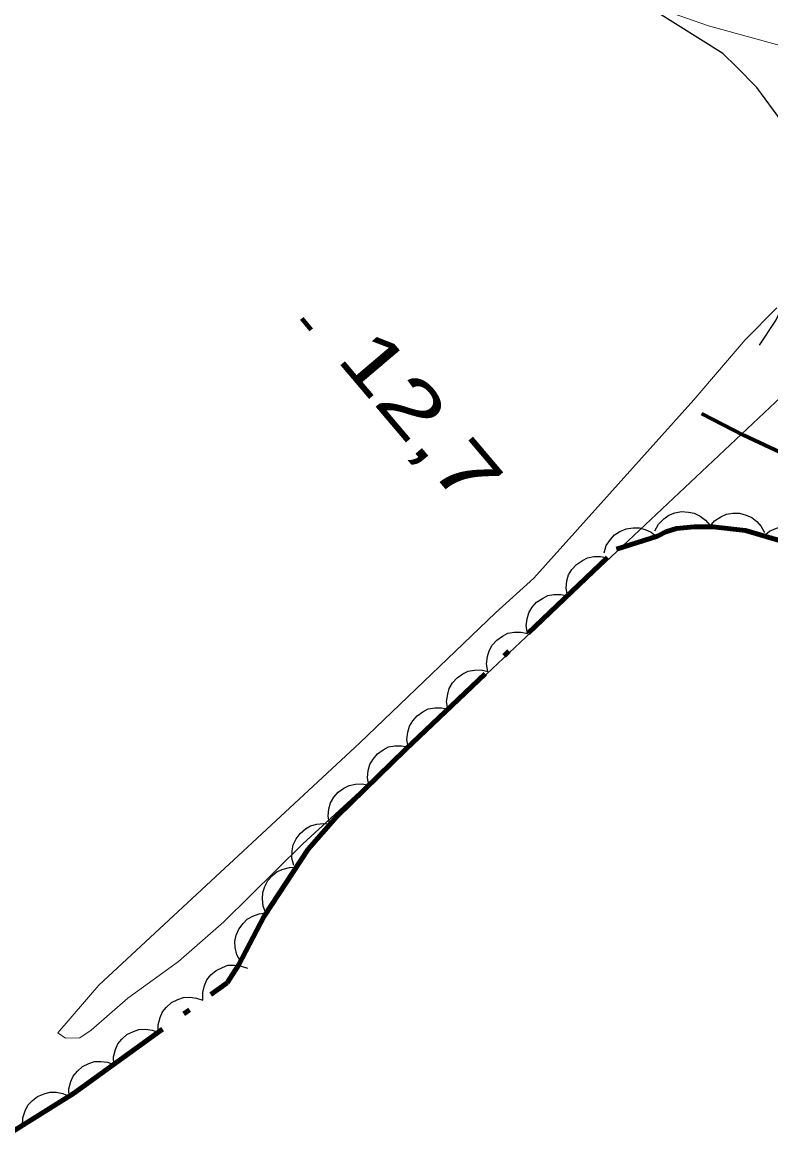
# Model space of a CAD drawing. Extents: x 386081 to 389416, y 5130568 to 5134082.
# Drawn here: x 387241.9 to 387282.8, y 5132643.6 to 5132704.2 of the extents above; entities that cross this region are included whole.
import ezdxf

# ---------------------------------------------------------------- set-up
doc = ezdxf.new("R2010")
doc.units = 0
doc.header["$LTSCALE"] = 1.2
doc.linetypes.add('DOT_DASHED', pattern=[7.7, 5, -1.2, 0.3, -1.2])
doc.linetypes.add('LONG_DASHED', pattern=[7.5, 6, -1.5])
for name, color, linetype, lineweight in [('2', 7, 'Continuous', 13), ('22', 7, 'Continuous', 13), ('3', 7, 'Continuous', 140), ('41', 7, 'DOT_DASHED', 25), ('44', 7, 'Continuous', 25)]:
    doc.layers.add(name, color=color, linetype=linetype, lineweight=lineweight)

msp = doc.modelspace()

# ---------------------------------------------------------------- linework, layer by layer
at = {"layer": '2'}
for points in [[(387274.72, 5132705.71), (387279.42, 5132704.05), (387284.4, 5132702.68)], [(387283.16, 5132688.63), (387281.42, 5132686.88), (387278.63, 5132683.61), (387269.88, 5132673.86), (387267.78, 5132671.97), (387260.36, 5132664.86), (387246.1, 5132651.63), (387243.86, 5132649.01), (387244.28, 5132648.73), (387245.06, 5132648.74), (387245.68, 5132649.16), (387247.69, 5132650.91), (387250.46, 5132652.92), (387252.93, 5132655.09), (387257.26, 5132659.34), (387264.51, 5132666), (387286.19, 5132686.4)]]:
    msp.add_lwpolyline(points, dxfattribs=at)
at = {"layer": '22', "linetype": 'LONG_DASHED', "lineweight": 70}
msp.add_lwpolyline([(387279.04, 5132682.86), (387281.33, 5132681.68), (387285.76, 5132679.6), (387289.92, 5132677.53), (387292.84, 5132676.22), (387296.88, 5132674.65), (387300.61, 5132673.65), (387306.21, 5132672.52), (387308.88, 5132671.71), (387311.06, 5132671.27), (387320.63, 5132669.01), (387322.87, 5132668.26), (387327.6, 5132667.26), (387331.52, 5132666.57), (387343.15, 5132663.62), (387345.2, 5132662.93), (387350.54, 5132660.55), (387357.31, 5132657.13), (387365.08, 5132652.95), (387368.5, 5132651.4), (387369.55, 5132650.96), (387374.41, 5132649.83)], dxfattribs=at)
at = {"layer": '3'}
msp.add_line((387257.2, 5132688.05), (387257.71, 5132687.44), dxfattribs=at)
at = {"layer": '41'}
msp.add_lwpolyline([(387282.22, 5132686.59), (387283.1, 5132687.95), (387283.98, 5132689.81), (387284.49, 5132691.29), (387284.77, 5132694.23), (387284.53, 5132695.72), (387284.05, 5132697.45), (387283.43, 5132698.82), (387282.07, 5132700.68), (387280.96, 5132701.8), (387280.21, 5132702.54), (387274.26, 5132706.27)], dxfattribs=at)
at = {"layer": '44'}
for points in [[(387276.5, 5132676.45), (387276.7, 5132676.82), (387276.99, 5132677.1), (387277.25, 5132677.3), (387277.58, 5132677.43), (387277.94, 5132677.5), (387278.33, 5132677.47), (387278.65, 5132677.42), (387278.96, 5132677.26), (387279.26, 5132677.03), (387279.49, 5132676.76)], [(387279.49, 5132676.68), (387279.76, 5132677), (387280.1, 5132677.22), (387280.4, 5132677.36), (387280.75, 5132677.41), (387281.12, 5132677.41), (387281.49, 5132677.3), (387281.79, 5132677.18), (387282.06, 5132676.96), (387282.31, 5132676.68), (387282.48, 5132676.36)], [(387273.72, 5132675.24), (387273.84, 5132675.64), (387274.07, 5132675.98), (387274.28, 5132676.23), (387274.58, 5132676.42), (387274.92, 5132676.56), (387275.3, 5132676.61), (387275.63, 5132676.62), (387275.96, 5132676.53), (387276.3, 5132676.37), (387276.58, 5132676.14)], [(387282.44, 5132676.17), (387282.76, 5132676.44), (387283.14, 5132676.6), (387283.46, 5132676.68), (387283.81, 5132676.67), (387284.17, 5132676.6), (387284.51, 5132676.43), (387284.79, 5132676.25), (387285.02, 5132675.98), (387285.21, 5132675.67), (387285.32, 5132675.32)], [(387271.71, 5132672.9), (387271.64, 5132673.31), (387271.69, 5132673.72), (387271.78, 5132674.04), (387271.96, 5132674.34), (387272.21, 5132674.61), (387272.53, 5132674.83), (387272.81, 5132674.98), (387273.16, 5132675.04), (387273.53, 5132675.05), (387273.88, 5132674.97)], [(387269.53, 5132670.84), (387269.46, 5132671.25), (387269.52, 5132671.65), (387269.6, 5132671.97), (387269.79, 5132672.27), (387270.03, 5132672.55), (387270.35, 5132672.76), (387270.64, 5132672.91), (387270.98, 5132672.97), (387271.36, 5132672.98), (387271.71, 5132672.9)], [(387267.36, 5132668.77), (387267.29, 5132669.18), (387267.34, 5132669.59), (387267.43, 5132669.9), (387267.61, 5132670.2), (387267.86, 5132670.48), (387268.17, 5132670.69), (387268.46, 5132670.85), (387268.81, 5132670.91), (387269.18, 5132670.91), (387269.53, 5132670.84)], [(387265.18, 5132666.7), (387265.11, 5132667.12), (387265.17, 5132667.52), (387265.25, 5132667.84), (387265.44, 5132668.14), (387265.68, 5132668.41), (387266, 5132668.63), (387266.29, 5132668.78), (387266.63, 5132668.84), (387267, 5132668.85), (387267.36, 5132668.77)], [(387263.01, 5132664.64), (387262.94, 5132665.05), (387262.99, 5132665.45), (387263.08, 5132665.77), (387263.26, 5132666.07), (387263.51, 5132666.35), (387263.82, 5132666.56), (387264.11, 5132666.72), (387264.46, 5132666.78), (387264.83, 5132666.78), (387265.18, 5132666.7)], [(387260.86, 5132662.55), (387260.78, 5132662.96), (387260.83, 5132663.36), (387260.91, 5132663.68), (387261.09, 5132663.98), (387261.33, 5132664.26), (387261.65, 5132664.48), (387261.93, 5132664.64), (387262.28, 5132664.7), (387262.65, 5132664.71), (387263, 5132664.64)], [(387258.71, 5132660.45), (387258.64, 5132660.86), (387258.68, 5132661.26), (387258.76, 5132661.58), (387258.95, 5132661.89), (387259.19, 5132662.17), (387259.5, 5132662.38), (387259.79, 5132662.54), (387260.13, 5132662.61), (387260.5, 5132662.62), (387260.86, 5132662.55)], [(387256.76, 5132658.16), (387256.66, 5132658.57), (387256.67, 5132658.97), (387256.73, 5132659.3), (387256.89, 5132659.62), (387257.11, 5132659.91), (387257.4, 5132660.16), (387257.68, 5132660.33), (387258.02, 5132660.43), (387258.38, 5132660.46), (387258.74, 5132660.42)], [(387255.24, 5132655.56), (387255.08, 5132655.94), (387255.04, 5132656.35), (387255.06, 5132656.68), (387255.17, 5132657.01), (387255.34, 5132657.34), (387255.6, 5132657.62), (387255.85, 5132657.83), (387256.17, 5132657.97), (387256.53, 5132658.06), (387256.89, 5132658.07)], [(387253.84, 5132652.91), (387253.64, 5132653.28), (387253.56, 5132653.68), (387253.54, 5132654.01), (387253.61, 5132654.35), (387253.76, 5132654.69), (387253.99, 5132655), (387254.21, 5132655.23), (387254.52, 5132655.4), (387254.87, 5132655.53), (387255.23, 5132655.57)], [(387251.79, 5132650.8), (387251.78, 5132651.22), (387251.88, 5132651.61), (387252.01, 5132651.91), (387252.23, 5132652.18), (387252.51, 5132652.42), (387252.86, 5132652.59), (387253.16, 5132652.71), (387253.52, 5132652.72), (387253.88, 5132652.67), (387254.22, 5132652.55)], [(387249.35, 5132649.05), (387249.34, 5132649.46), (387249.45, 5132649.86), (387249.58, 5132650.16), (387249.8, 5132650.43), (387250.08, 5132650.67), (387250.42, 5132650.84), (387250.73, 5132650.95), (387251.08, 5132650.97), (387251.45, 5132650.92), (387251.79, 5132650.8)], [(387246.92, 5132647.29), (387246.91, 5132647.71), (387247.01, 5132648.1), (387247.14, 5132648.41), (387247.36, 5132648.68), (387247.64, 5132648.92), (387247.99, 5132649.09), (387248.29, 5132649.2), (387248.65, 5132649.21), (387249.01, 5132649.17), (387249.35, 5132649.05)], [(387244.48, 5132645.54), (387244.47, 5132645.96), (387244.58, 5132646.35), (387244.71, 5132646.65), (387244.93, 5132646.93), (387245.21, 5132647.17), (387245.55, 5132647.34), (387245.86, 5132647.45), (387246.21, 5132647.46), (387246.58, 5132647.42), (387246.92, 5132647.29)], [(387241.93, 5132643.96), (387241.95, 5132644.38), (387242.08, 5132644.76), (387242.22, 5132645.06), (387242.47, 5132645.32), (387242.76, 5132645.54), (387243.11, 5132645.69), (387243.43, 5132645.78), (387243.78, 5132645.77), (387244.14, 5132645.7), (387244.47, 5132645.56)]]:
    msp.add_lwpolyline(points, dxfattribs=at)
at = {"layer": '44', "linetype": 'DOT_DASHED', "lineweight": 90}
msp.add_lwpolyline([(387241.37, 5132643.61), (387244.72, 5132645.71), (387253.11, 5132651.75), (387253.73, 5132652.71), (387255.14, 5132655.4), (387257.54, 5132659.05), (387259.11, 5132660.84), (387262.86, 5132664.5), (387274.39, 5132675.45), (387276.63, 5132676.16), (387277.09, 5132676.4), (387277.67, 5132676.57), (387278.64, 5132676.67), (387279.66, 5132676.66), (387281.44, 5132676.47), (387286.61, 5132674.94)], dxfattribs=at)

# ---------------------------------------------------------------- texts
at = {"layer": '3', "width": 1.4}
msp.add_text('12,7   ', height=3, rotation=310.294, dxfattribs=at).set_placement((387259.03, 5132685.83))

doc.saveas('drawing.dxf')
